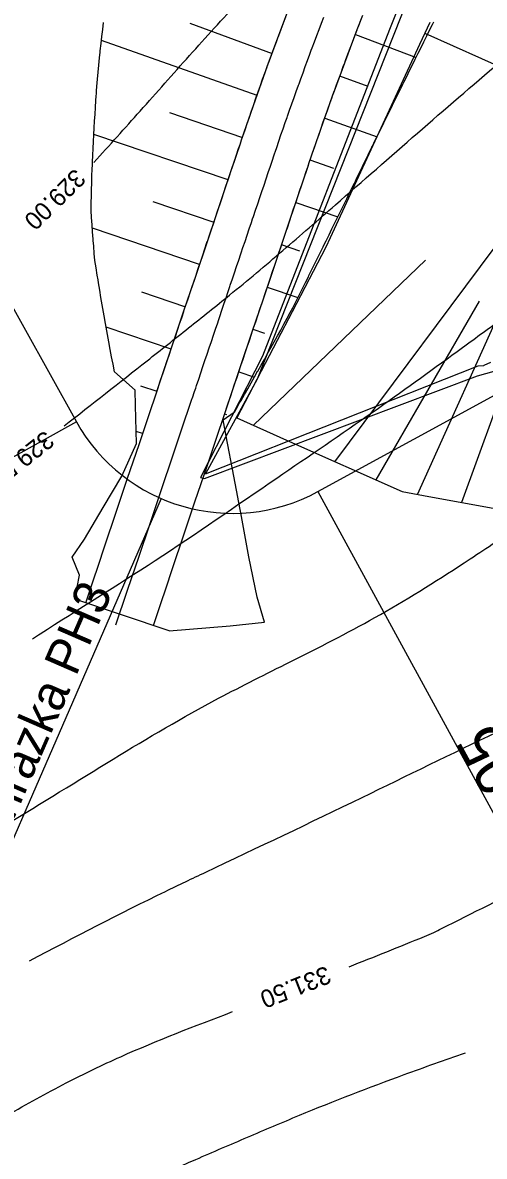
# Model space of a CAD drawing. Extents: x -564037 to -563827, y -1163561 to -1163412.
# Drawn here: x -563905.42 to -563892.49, y -1163524.87 to -1163493.12 of the extents above; entities that cross this region are included whole.
import ezdxf

# ---------------------------------------------------------------- set-up
doc = ezdxf.new("R2010")
doc.units = 0
for name, color, linetype in [('5', 7, 'Continuous'), ('_popis staničení RT1', 7, 'Continuous'), ('Default', 7, 'Continuous'), ('Line', 7, 'Continuous'), ('Vrstva 24', 7, 'Continuous'), ('Vrstva 25', 7, 'Continuous'), ('Vrstva 26', 7, 'Continuous')]:
    doc.layers.add(name, color=color, linetype=linetype)

msp = doc.modelspace()

# ---------------------------------------------------------------- linework, layer by layer
for p, q in [((-563890.151, -1163481.173), (-563898.85, -1163503.099)), ((-563898.85, -1163503.099), (-563900.295, -1163505.749))]:
    msp.add_line(p, q)
msp.add_lwpolyline([(-563900.324, -1163505.882), (-563892.678, -1163503.006), (-563888.735, -1163501.906), (-563886.271, -1163502.018), (-563883.536, -1163500.684), (-563878.095, -1163497.234), (-563876.621, -1163489.849), (-563880.163, -1163485.998), (-563881.977, -1163484.515), (-563883.765, -1163483.269), (-563890.133, -1163481.092), (-563891.974, -1163485.382), (-563895.143, -1163493.304), (-563898.704, -1163502.458), (-563900.439, -1163505.855)], close=True)
for points in [[(-563901.709, -1163503.594), (-563901.519, -1163503.03), (-563901.312, -1163502.416), (-563901.2, -1163502.083), (-563900.88, -1163501.135), (-563900.561, -1163500.187), (-563900.242, -1163499.24), (-563899.923, -1163498.292), (-563899.604, -1163497.344), (-563899.329, -1163496.528), (-563899.284, -1163496.395), (-563898.956, -1163495.44), (-563898.618, -1163494.488), (-563898.566, -1163494.344), (-563898.27, -1163493.54), (-563897.913, -1163492.595)], [(-563903.651, -1163509.364), (-563903.434, -1163508.717), (-563903.304, -1163508.333), (-563903.114, -1163507.769), (-563902.795, -1163506.821), (-563902.476, -1163505.873), (-563902.157, -1163504.926), (-563901.838, -1163503.978), (-563901.709, -1163503.594), (-563901.613, -1163503.31), (-563901.612, -1163503.306), (-563901.552, -1163503.131), (-563901.519, -1163503.03), (-563901.493, -1163502.955), (-563901.434, -1163502.78), (-563901.375, -1163502.605), (-563901.316, -1163502.429), (-563901.257, -1163502.254), (-563901.2, -1163502.083), (-563901.198, -1163502.079), (-563901.139, -1163501.904), (-563901.08, -1163501.728), (-563901.021, -1163501.553), (-563900.962, -1163501.378), (-563900.903, -1163501.202), (-563900.88, -1163501.135), (-563900.844, -1163501.027), (-563900.785, -1163500.852), (-563900.726, -1163500.676), (-563900.667, -1163500.501), (-563900.608, -1163500.326), (-563900.561, -1163500.187), (-563900.549, -1163500.15), (-563900.49, -1163499.975), (-563900.431, -1163499.8), (-563900.372, -1163499.624), (-563900.313, -1163499.449), (-563900.254, -1163499.274), (-563900.242, -1163499.24), (-563900.194, -1163499.098), (-563900.135, -1163498.923), (-563900.076, -1163498.748), (-563900.017, -1163498.572), (-563899.958, -1163498.397), (-563899.923, -1163498.292), (-563899.899, -1163498.222), (-563899.84, -1163498.046), (-563899.781, -1163497.871), (-563899.722, -1163497.696), (-563899.663, -1163497.52), (-563899.604, -1163497.345), (-563899.604, -1163497.344), (-563899.545, -1163497.17), (-563899.486, -1163496.994), (-563899.427, -1163496.819), (-563899.368, -1163496.644), (-563899.329, -1163496.528), (-563899.309, -1163496.468), (-563899.284, -1163496.395), (-563899.249, -1163496.291), (-563899.188, -1163496.114), (-563899.128, -1163495.937), (-563899.067, -1163495.761), (-563899.006, -1163495.584), (-563898.956, -1163495.44), (-563898.944, -1163495.408), (-563898.882, -1163495.231), (-563898.82, -1163495.055), (-563898.758, -1163494.879), (-563898.695, -1163494.703), (-563898.632, -1163494.527), (-563898.618, -1163494.488), (-563898.568, -1163494.351), (-563898.566, -1163494.344), (-563898.504, -1163494.176), (-563898.44, -1163494), (-563898.376, -1163493.825), (-563898.311, -1163493.65), (-563898.27, -1163493.54), (-563898.246, -1163493.475), (-563898.18, -1163493.3), (-563898.115, -1163493.125), (-563898.048, -1163492.95)], [(-563902.805, -1163509.983), (-563902.486, -1163509.036), (-563902.357, -1163508.652), (-563902.167, -1163508.088), (-563901.848, -1163507.14), (-563901.528, -1163506.193), (-563901.209, -1163505.245), (-563900.89, -1163504.297), (-563900.761, -1163503.913), (-563900.665, -1163503.629), (-563900.664, -1163503.625), (-563900.605, -1163503.45), (-563900.571, -1163503.349), (-563900.546, -1163503.275), (-563900.487, -1163503.099), (-563900.428, -1163502.924), (-563900.369, -1163502.749), (-563900.31, -1163502.573), (-563900.252, -1163502.402), (-563900.251, -1163502.398), (-563900.191, -1163502.223), (-563900.132, -1163502.047), (-563900.073, -1163501.872), (-563900.014, -1163501.697), (-563899.955, -1163501.521), (-563899.933, -1163501.454), (-563899.896, -1163501.346), (-563899.837, -1163501.171), (-563899.778, -1163500.995), (-563899.719, -1163500.82), (-563899.66, -1163500.645), (-563899.613, -1163500.506), (-563899.601, -1163500.469), (-563899.542, -1163500.294), (-563899.483, -1163500.119), (-563899.424, -1163499.943), (-563899.365, -1163499.768), (-563899.306, -1163499.593), (-563899.294, -1163499.559), (-563899.247, -1163499.417), (-563899.188, -1163499.242), (-563899.129, -1163499.067), (-563899.07, -1163498.891), (-563899.011, -1163498.716), (-563898.975, -1163498.611), (-563898.952, -1163498.541), (-563898.893, -1163498.366), (-563898.833, -1163498.19), (-563898.774, -1163498.015), (-563898.715, -1163497.84), (-563898.656, -1163497.664), (-563898.656, -1163497.663), (-563898.597, -1163497.489), (-563898.538, -1163497.314), (-563898.479, -1163497.138), (-563898.42, -1163496.963), (-563898.381, -1163496.847), (-563898.361, -1163496.788), (-563898.337, -1163496.716), (-563898.302, -1163496.612), (-563898.242, -1163496.437), (-563898.182, -1163496.262), (-563898.122, -1163496.087), (-563898.061, -1163495.913), (-563898.012, -1163495.77), (-563898, -1163495.738), (-563897.939, -1163495.563), (-563897.878, -1163495.389), (-563897.816, -1163495.215), (-563897.753, -1163495.04), (-563897.691, -1163494.866), (-563897.677, -1163494.828), (-563897.628, -1163494.692), (-563897.625, -1163494.685), (-563897.565, -1163494.518), (-563897.501, -1163494.345), (-563897.437, -1163494.171), (-563897.373, -1163493.997), (-563897.333, -1163493.889), (-563897.309, -1163493.824), (-563897.244, -1163493.651), (-563897.179, -1163493.478), (-563897.113, -1163493.305), (-563897.048, -1163493.132), (-563896.982, -1163492.959)], [(-563901.756, -1163510.002), (-563901.538, -1163509.355), (-563901.409, -1163508.971), (-563901.219, -1163508.407), (-563900.9, -1163507.459), (-563900.581, -1163506.512), (-563900.262, -1163505.564), (-563899.942, -1163504.616), (-563899.813, -1163504.233), (-563899.717, -1163503.948), (-563899.716, -1163503.944), (-563899.657, -1163503.769), (-563899.623, -1163503.669), (-563899.598, -1163503.594), (-563899.539, -1163503.418), (-563899.48, -1163503.243), (-563899.421, -1163503.068), (-563899.362, -1163502.892), (-563899.304, -1163502.721), (-563899.303, -1163502.717), (-563899.244, -1163502.542), (-563899.185, -1163502.367), (-563899.126, -1163502.191), (-563899.067, -1163502.016), (-563899.008, -1163501.841), (-563898.985, -1163501.773), (-563898.949, -1163501.665), (-563898.89, -1163501.49), (-563898.83, -1163501.315), (-563898.771, -1163501.139), (-563898.712, -1163500.964), (-563898.666, -1163500.826), (-563898.653, -1163500.789), (-563898.594, -1163500.613), (-563898.535, -1163500.438), (-563898.476, -1163500.263), (-563898.417, -1163500.087), (-563898.358, -1163499.912), (-563898.347, -1163499.878), (-563898.299, -1163499.737), (-563898.24, -1163499.561), (-563898.181, -1163499.386), (-563898.122, -1163499.211), (-563898.063, -1163499.035), (-563898.027, -1163498.93), (-563898.004, -1163498.86), (-563897.945, -1163498.685), (-563897.886, -1163498.509), (-563897.827, -1163498.334), (-563897.768, -1163498.159), (-563897.709, -1163497.983), (-563897.708, -1163497.982), (-563897.65, -1163497.808), (-563897.591, -1163497.633), (-563897.532, -1163497.457), (-563897.472, -1163497.282), (-563897.433, -1163497.166), (-563897.414, -1163497.107), (-563897.39, -1163497.036), (-563897.355, -1163496.934), (-563897.296, -1163496.76), (-563897.236, -1163496.587), (-563897.177, -1163496.414), (-563897.117, -1163496.241), (-563897.068, -1163496.1), (-563897.056, -1163496.068), (-563896.996, -1163495.895), (-563896.935, -1163495.723), (-563896.874, -1163495.55), (-563896.812, -1163495.378), (-563896.75, -1163495.205), (-563896.736, -1163495.167), (-563896.688, -1163495.033), (-563896.685, -1163495.026), (-563896.625, -1163494.861), (-563896.562, -1163494.689), (-563896.499, -1163494.517), (-563896.436, -1163494.345), (-563896.396, -1163494.237), (-563896.372, -1163494.173), (-563896.308, -1163494.002), (-563896.243, -1163493.83), (-563896.178, -1163493.659), (-563896.113, -1163493.488), (-563896.048, -1163493.317), (-563896.046, -1163493.311), (-563895.982, -1163493.146), (-563895.916, -1163492.975)], [(-563899.813, -1163504.233), (-563899.623, -1163503.669), (-563899.417, -1163503.055), (-563899.304, -1163502.721), (-563898.985, -1163501.773), (-563898.666, -1163500.826), (-563898.347, -1163499.878), (-563898.027, -1163498.93), (-563897.708, -1163497.982), (-563897.433, -1163497.166), (-563897.39, -1163497.036), (-563897.068, -1163496.1), (-563896.736, -1163495.167), (-563896.685, -1163495.026), (-563896.396, -1163494.237), (-563896.046, -1163493.311), (-563895.888, -1163492.903)], [(-563899.803, -1163504.236), (-563899.49, -1163504.025), (-563899.488, -1163504.021), (-563899.394, -1163503.858), (-563899.34, -1163503.764), (-563899.3, -1163503.694), (-563899.206, -1163503.531), (-563899.113, -1163503.367), (-563899.019, -1163503.203), (-563898.926, -1163503.039), (-563898.835, -1163502.879), (-563898.833, -1163502.875), (-563898.74, -1163502.711), (-563898.648, -1163502.547), (-563898.555, -1163502.383), (-563898.463, -1163502.219), (-563898.371, -1163502.055), (-563898.336, -1163501.992), (-563898.28, -1163501.89), (-563898.19, -1163501.725), (-563898.1, -1163501.561), (-563898.01, -1163501.396), (-563897.92, -1163501.231), (-563897.853, -1163501.099), (-563897.835, -1163501.064), (-563897.75, -1163500.897), (-563897.666, -1163500.731), (-563897.582, -1163500.564), (-563897.499, -1163500.397), (-563897.415, -1163500.23), (-563897.399, -1163500.197), (-563897.332, -1163500.062), (-563897.249, -1163499.895), (-563897.166, -1163499.728), (-563897.083, -1163499.561), (-563897, -1163499.393), (-563896.951, -1163499.293), (-563896.918, -1163499.226), (-563896.836, -1163499.058), (-563896.754, -1163498.891), (-563896.671, -1163498.723), (-563896.588, -1163498.556), (-563896.506, -1163498.388), (-563896.505, -1163498.388), (-563896.424, -1163498.221), (-563896.342, -1163498.053), (-563896.26, -1163497.886), (-563896.178, -1163497.718), (-563896.124, -1163497.607), (-563896.097, -1163497.552), (-563896.065, -1163497.484), (-563896.018, -1163497.388), (-563895.938, -1163497.224), (-563895.858, -1163497.061), (-563895.779, -1163496.897), (-563895.699, -1163496.734), (-563895.634, -1163496.601), (-563895.619, -1163496.571), (-563895.54, -1163496.408), (-563895.46, -1163496.245), (-563895.38, -1163496.082), (-563895.3, -1163495.919), (-563895.22, -1163495.756), (-563895.202, -1163495.72), (-563895.14, -1163495.594), (-563895.137, -1163495.587), (-563895.06, -1163495.431), (-563894.98, -1163495.269), (-563894.9, -1163495.106), (-563894.82, -1163494.944), (-563894.77, -1163494.842), (-563894.74, -1163494.782), (-563894.66, -1163494.62), (-563894.58, -1163494.458), (-563894.5, -1163494.296), (-563894.42, -1163494.134), (-563894.339, -1163493.972), (-563894.337, -1163493.967), (-563894.259, -1163493.81), (-563894.179, -1163493.649), (-563894.145, -1163493.581), (-563894.099, -1163493.487), (-563894.019, -1163493.325), (-563893.939, -1163493.164), (-563893.904, -1163493.093)], [(-563902.226, -1163504.902), (-563902.261, -1163503.836), (-563902.265, -1163503.407), (-563902.843, -1163502.896), (-563902.843, -1163502.891), (-563902.884, -1163502.682), (-563902.907, -1163502.563), (-563902.924, -1163502.474), (-563902.964, -1163502.265), (-563903.002, -1163502.057), (-563903.041, -1163501.849), (-563903.078, -1163501.641), (-563903.115, -1163501.438), (-563903.115, -1163501.433), (-563903.152, -1163501.226), (-563903.188, -1163501.018), (-563903.223, -1163500.811), (-563903.258, -1163500.604), (-563903.292, -1163500.398), (-563903.305, -1163500.318), (-563903.326, -1163500.191), (-563903.359, -1163499.985), (-563903.391, -1163499.779), (-563903.411, -1163499.577), (-563903.427, -1163499.376), (-563903.439, -1163499.218), (-563903.442, -1163499.176), (-563903.457, -1163498.976), (-563903.471, -1163498.776), (-563903.485, -1163498.576), (-563903.498, -1163498.376), (-563903.499, -1163498.181), (-563903.498, -1163498.143), (-563903.493, -1163497.987), (-563903.488, -1163497.794), (-563903.482, -1163497.601), (-563903.475, -1163497.408), (-563903.468, -1163497.215), (-563903.463, -1163497.1), (-563903.46, -1163497.023), (-563903.451, -1163496.83), (-563903.442, -1163496.638), (-563903.433, -1163496.446), (-563903.423, -1163496.254), (-563903.413, -1163496.062), (-563903.413, -1163496.061), (-563903.402, -1163495.871), (-563903.39, -1163495.68), (-563903.378, -1163495.489), (-563903.365, -1163495.298), (-563903.357, -1163495.171), (-563903.352, -1163495.104), (-563903.345, -1163495.021), (-563903.336, -1163494.903), (-563903.319, -1163494.703), (-563903.302, -1163494.503), (-563903.283, -1163494.303), (-563903.263, -1163494.103), (-563903.246, -1163493.94), (-563903.242, -1163493.904), (-563903.221, -1163493.704), (-563903.198, -1163493.505), (-563903.174, -1163493.306), (-563903.149, -1163493.108)], [(-563900.295, -1163505.749), (-563892.658, -1163502.726), (-563892.5, -1163502.714), (-563892.491, -1163502.712), (-563892.306, -1163502.622)], [(-563901.311, -1163510.152), (-563899.601, -1163510.007), (-563898.639, -1163509.904), (-563898.845, -1163509.207), (-563899.079, -1163508.073), (-563899.291, -1163506.946), (-563899.504, -1163505.819), (-563899.717, -1163504.692), (-563899.803, -1163504.236)], [(-563901.311, -1163510.152), (-563903.956, -1163509.261), (-563903.825, -1163508.585), (-563904.027, -1163508.089), (-563903.682, -1163507.578), (-563903.161, -1163506.698), (-563902.64, -1163505.818), (-563902.226, -1163504.902)]]:
    msp.add_lwpolyline(points)
at = {"layer": '5'}
for p, q in [((-563921.324, -1163473.035), (-563903.913, -1163504.291)), ((-563897.15, -1163506.247), (-563862.812, -1163487.513))]:
    msp.add_line(p, q, dxfattribs=at)
msp.add_arc((-563899.545, -1163501.858), 5, 209.1194, 298.6163, dxfattribs=at)
at = {"layer": '_popis staničení RT1'}
for points in [[(-563903.913, -1163504.291), (-563917.017, -1163511.59)], [(-563897.15, -1163506.247), (-563889.966, -1163519.415)], [(-563901.539, -1163506.443), (-563909.435, -1163524.593)]]:
    msp.add_lwpolyline(points, dxfattribs=at)
at = {"layer": 'Default'}
msp.add_lwpolyline([(-563894.011, -1163493.107), (-563894.298, -1163493.726), (-563896.807, -1163499.145), (-563896.925, -1163499.399), (-563897.869, -1163501.213), (-563898.286, -1163502.014), (-563899.415, -1163504.184), (-563898.029, -1163504.804), (-563894.792, -1163506.25), (-563894.189, -1163506.359), (-563890.445, -1163507.038), (-563890.304, -1163507.064), (-563887.435, -1163506.214), (-563885.296, -1163505.58), (-563883.769, -1163504.643), (-563881.393, -1163503.187), (-563879.621, -1163502.1), (-563877.447, -1163498.123), (-563877.26, -1163497.64), (-563876.56, -1163495.83), (-563876.213, -1163494.931), (-563876.002, -1163494.387), (-563875.979, -1163493.391), (-563875.957, -1163492.484)], dxfattribs=at)
at = {"layer": 'Line'}
for p, q in [((-563900.732, -1163493.131), (-563898.43, -1163493.976)), ((-563894.152, -1163493.411), (-563889.486, -1163495.501)), ((-563898.853, -1163495.152), (-563903.21, -1163493.612)), ((-563896.095, -1163493.444), (-563894.399, -1163494.092)), ((-563895.74, -1163494.906), (-563896.534, -1163494.614)), ((-563901.301, -1163495.636), (-563899.263, -1163496.333)), ((-563896.958, -1163495.79), (-563895.491, -1163496.309)), ((-563896.67, -1163505.411), (-563889.53, -1163495.82)), ((-563894.356, -1163506.329), (-563889.596, -1163495.749)), ((-563899.662, -1163497.517), (-563903.423, -1163496.25)), ((-563896.702, -1163497.198), (-563897.367, -1163496.971)), ((-563901.77, -1163498.126), (-563900.061, -1163498.702)), ((-563897.767, -1163498.156), (-563896.587, -1163498.553)), ((-563900.46, -1163499.886), (-563903.464, -1163498.875)), ((-563897.655, -1163499.512), (-563898.166, -1163499.34)), ((-563898.953, -1163504.391), (-563894.136, -1163499.765)), ((-563902.088, -1163500.657), (-563900.859, -1163501.071)), ((-563898.565, -1163500.525), (-563897.708, -1163500.813)), ((-563892.627, -1163500.918), (-563895.529, -1163505.921)), ((-563891.196, -1163501.236), (-563893.126, -1163506.552)), ((-563901.258, -1163502.256), (-563903.078, -1163501.643)), ((-563898.633, -1163501.821), (-563898.963, -1163501.709)), ((-563899.362, -1163502.894), (-563898.927, -1163503.041)), ((-563902.117, -1163503.285), (-563901.657, -1163503.44)), ((-563899.698, -1163504.1), (-563899.761, -1163504.079)), ((-563902.056, -1163504.625), (-563902.237, -1163504.564))]:
    msp.add_line(p, q, dxfattribs=at)
at = {"layer": 'Vrstva 24'}
for points in [[(-563903.419, -1163497.029), (-563902.125, -1163495.59), (-563900.744, -1163494.039), (-563899.345, -1163492.505), (-563898.448, -1163491.553), (-563897.897, -1163490.941), (-563897.635, -1163490.622), (-563897.383, -1163490.29), (-563897.001, -1163489.401), (-563896.398, -1163486.71), (-563896.305, -1163486.212), (-563896.276, -1163485.962), (-563896.268, -1163485.713), (-563896.394, -1163485.294), (-563896.666, -1163484.924), (-563897.969, -1163483.548), (-563899.309, -1163482.237), (-563900.743, -1163480.898), (-563903.659, -1163478.289), (-563907.403, -1163474.951), (-563909.511, -1163473.024), (-563914.099, -1163468.742), (-563916.271, -1163466.637)], [(-563905.221, -1163519.388), (-563901.417, -1163517.444), (-563900.291, -1163516.907), (-563895.909, -1163514.815), (-563892.135, -1163512.984), (-563890.63, -1163512.267), (-563888.864, -1163511.357), (-563887.99, -1163510.869), (-563887.125, -1163510.367), (-563886.26, -1163509.866), (-563885.383, -1163509.384), (-563882.362, -1163507.826), (-563880.585, -1163506.938), (-563878.549, -1163505.818), (-563872.848, -1163502.599), (-563870.632, -1163501.288), (-563869.542, -1163500.601), (-563868.575, -1163499.969)], [(-563931.161, -1163537.124), (-563928.768, -1163536.86), (-563922.688, -1163536.158), (-563922.482, -1163536.112), (-563922.145, -1163535.991), (-563913.265, -1163532.02), (-563912.083, -1163531.357), (-563910.91, -1163530.589), (-563907.314, -1163528.363), (-563903.77, -1163526.446), (-563900.567, -1163524.953), (-563899.119, -1163524.329), (-563897.667, -1163523.716), (-563894.732, -1163522.576), (-563893.017, -1163521.965)]]:
    msp.add_spline(points, degree=3, dxfattribs=at)
at = {"layer": 'Vrstva 25'}
msp.add_spline([(-563905.141, -1163510.37), (-563904.922, -1163510.229), (-563901.706, -1163508.177), (-563898.297, -1163505.868), (-563895.6, -1163504.013), (-563893.249, -1163502.324), (-563892.081, -1163501.469), (-563890.919, -1163500.608), (-563889.757, -1163499.746), (-563888.589, -1163498.892), (-563887.491, -1163498.145), (-563886.364, -1163497.441), (-563885.229, -1163496.747), (-563884.107, -1163496.03), (-563883.48, -1163495.59), (-563883.181, -1163495.349), (-563882.893, -1163495.092), (-563882.209, -1163494.336), (-563881.626, -1163493.502), (-563881.193, -1163492.783), (-563880.36, -1163491.213), (-563880.004, -1163490.417), (-563879.711, -1163489.616), (-563879.829, -1163489.186), (-563884.789, -1163483.345)], degree=3, dxfattribs=at)
at = {"layer": 'Vrstva 26'}
for points in [[(-563904.255, -1163504.408), (-563901.932, -1163502.584), (-563900.774, -1163501.667), (-563899.621, -1163500.744), (-563898.128, -1163499.495), (-563896.658, -1163498.219), (-563892.051, -1163494.217), (-563891.058, -1163493.351), (-563890.3, -1163492.602), (-563889.946, -1163492.201), (-563889.6, -1163491.789), (-563889.274, -1163491.333), (-563889.128, -1163491.092), (-563888.986, -1163490.845), (-563888.757, -1163490.393), (-563888.565, -1163489.929), (-563888.402, -1163489.454), (-563888.258, -1163488.97), (-563888.179, -1163488.634), (-563888.132, -1163488.29), (-563888.126, -1163487.946), (-563888.168, -1163487.609), (-563888.372, -1163487.087), (-563888.888, -1163486.275), (-563889.418, -1163485.493), (-563889.974, -1163484.737), (-563890.569, -1163484.004), (-563892.45, -1163481.915), (-563894.839, -1163479.601), (-563896.896, -1163477.665), (-563897.939, -1163476.713), (-563899, -1163475.779), (-563899.292, -1163475.563), (-563900.233, -1163474.949)], [(-563906.28, -1163515.803), (-563905.884, -1163515.571), (-563902.883, -1163513.741), (-563899.929, -1163512.038), (-563897.928, -1163511.018), (-563895.553, -1163509.778), (-563893.055, -1163508.246), (-563892.353, -1163507.782), (-563891.657, -1163507.311), (-563890.96, -1163506.841), (-563890.257, -1163506.379), (-563888.16, -1163505.094), (-563886.21, -1163504.031), (-563880.965, -1163501.085), (-563878.454, -1163499.578), (-563877.23, -1163498.772), (-563876.032, -1163497.922), (-563874.901, -1163496.941), (-563873.614, -1163495.651), (-563873.276, -1163495.107), (-563873.154, -1163494.587), (-563873.048, -1163494.066), (-563872.865, -1163493.019), (-563872.827, -1163492.778)], [(-563896.274, -1163519.554), (-563894.165, -1163518.707), (-563893.901, -1163518.593), (-563893.686, -1163518.487), (-563888.411, -1163515.922), (-563883.796, -1163513.845), (-563882.856, -1163513.463), (-563881.551, -1163512.898), (-563877.829, -1163511.052), (-563874.459, -1163509.5), (-563873.358, -1163509.055), (-563872.244, -1163508.643), (-563871.128, -1163508.237), (-563870.019, -1163507.811), (-563865.656, -1163505.903), (-563863.431, -1163504.67), (-563862.373, -1163503.951), (-563861.332, -1163503.174), (-563860.403, -1163502.078), (-563859.968, -1163500.761)], [(-563938.247, -1163534.094), (-563936.943, -1163534.069), (-563931.73, -1163533.621), (-563930.272, -1163533.423), (-563929.328, -1163533.288), (-563925.493, -1163532.585), (-563923.592, -1163532.141), (-563921.698, -1163531.646), (-563918.724, -1163530.654), (-563917.276, -1163530.052), (-563915.858, -1163529.378), (-563913.985, -1163528.389), (-563912.146, -1163527.347), (-563909.112, -1163525.55), (-563905.848, -1163523.712), (-563904.199, -1163522.809), (-563902.671, -1163522.075), (-563899.54, -1163520.813)], [(-563925.566, -1163540.094), (-563923.701, -1163539.76), (-563920.879, -1163539.007), (-563915.972, -1163537.466), (-563914.453, -1163536.78), (-563910.376, -1163534.207), (-563906.396, -1163531.612), (-563905.564, -1163531.1), (-563904.749, -1163530.666), (-563896.797, -1163526.869), (-563895.69, -1163526.354), (-563895.369, -1163526.239), (-563890.229, -1163524.652), (-563887.69, -1163523.91)]]:
    msp.add_spline(points, degree=3, dxfattribs=at)

# ---------------------------------------------------------------- texts
at = {"layer": '_popis staničení RT1'}
for s, height, rotation, p in [('0+121 50 Zemní hrázka PH3', 1, 66.4909, (-563909.724, -1163524.774)), ('0+126.05', 1.25, 118.6163, (-563888.868, -1163518.816))]:
    msp.add_text(s, height=height, rotation=rotation, dxfattribs=at).set_placement(p)
at = {"layer": 'Vrstva 25'}
for s, rotation, p in [('329.00', 224.4524, (-563903.955, -1163497.176)), ('329.50', 218.2138, (-563904.791, -1163504.516)), ('331.50', 201.5654, (-563896.912, -1163519.52))]:
    msp.add_text(s, height=0.5, rotation=rotation, dxfattribs=at).set_placement(p)

doc.saveas('drawing.dxf')
